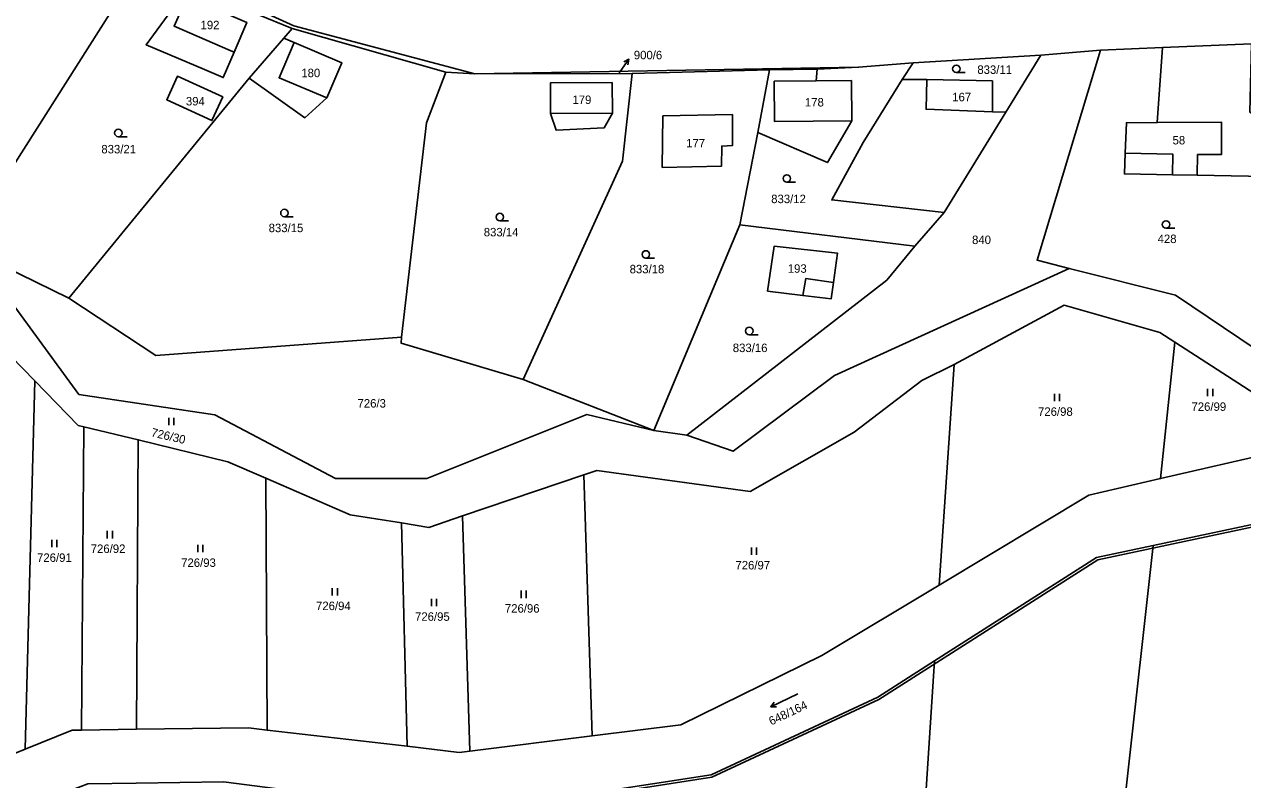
# Model space of a CAD drawing. Extents: x -654083 to -650132, y -1099819 to -1096699.
# Drawn here: x -652530.5 to -652286.2, y -1098583.8 to -1098432.3 of the extents above; entities that cross this region are included whole.
import ezdxf

# ---------------------------------------------------------------- set-up
doc = ezdxf.new("R2010")
doc.units = 0
for name, color, linetype in [('Hranice - vnitř_ kresba', 7, 'Continuous'), ('Obvody jako plochy', 7, 'Continuous'), ('Ostatní hranice', 7, 'Continuous'), ('Parcelní čísla', 7, 'Continuous'), ('Prvky pro prodl_ par_ č_', 7, 'Continuous'), ('Značky kultur', 7, 'Continuous')]:
    doc.layers.add(name, color=color, linetype=linetype)

msp = doc.modelspace()

# ---------------------------------------------------------------- linework, layer by layer
at = {"layer": 'Hranice - vnitř_ kresba'}
for p, q in [((-652497.86, -1098426.73), (-652500.48, -1098432.67)), ((-652500.48, -1098432.67), (-652489.23, -1098437.54)), ((-652489.23, -1098437.54), (-652488.44, -1098437.88)), ((-652476.41, -1098435.96), (-652479.41, -1098443.01)), ((-652479.41, -1098443.01), (-652469.86, -1098447.07)), ((-652380.17, -1098443.71), (-652371.72, -1098443.64)), ((-652380.17, -1098443.71), (-652380.11, -1098451.76)), ((-652349.71, -1098449.33), (-652349.57, -1098443.34)), ((-652349.71, -1098449.33), (-652336.41, -1098449.82)), ((-652424.99, -1098450.19), (-652412.59, -1098450.14)), ((-652380.11, -1098451.76), (-652364.62, -1098451.64)), ((-652303.36, -1098452.01), (-652290.45, -1098451.94)), ((-652290.5, -1098458.42), (-652290.45, -1098451.94)), ((-652309.8, -1098458.12), (-652300.27, -1098458.32)), ((-652300.27, -1098458.32), (-652300.32, -1098462.48)), ((-652295.28, -1098458.4), (-652295.33, -1098462.57)), ((-652295.28, -1098458.4), (-652290.5, -1098458.42)), ((-652373.84, -1098483.29), (-652374.4, -1098486.68)), ((-652368.28, -1098484.06), (-652373.84, -1098483.29))]:
    msp.add_line(p, q, dxfattribs=at)
at = {"layer": 'Obvody jako plochy'}
for points in [[(-652446, -1098441.91), (-652476.82, -1098433.16), (-652497.47, -1098424.65), (-652506.82, -1098419.78), (-652532.27, -1098406.94), (-652542.32, -1098403.58), (-652559.94, -1098399.93), (-652559.53, -1098399.2), (-652541.49, -1098401.98), (-652529.79, -1098405.93), (-652498.81, -1098422.38), (-652476.45, -1098432.57), (-652440.16, -1098442.2)], [(-652560.42, -1098472.15), (-652543.42, -1098477.5), (-652506.82, -1098419.78), (-652532.27, -1098406.94), (-652577.66, -1098473.77), (-652576.42, -1098473.9), (-652564.53, -1098474.44)], [(-652521.58, -1098487.25), (-652541.39, -1098477.54), (-652542.49, -1098478.23), (-652543.42, -1098477.5), (-652506.82, -1098419.78), (-652497.47, -1098424.65), (-652476.82, -1098433.16), (-652478.48, -1098435.08), (-652485.44, -1098443.08)], [(-652497.86, -1098426.73), (-652485.89, -1098431.92), (-652488.44, -1098437.88), (-652490.62, -1098442.98), (-652494.35, -1098441.39), (-652499.59, -1098439.16), (-652506.07, -1098436.4), (-652498.69, -1098426.32)], [(-652490.62, -1098442.98), (-652494.35, -1098441.39), (-652499.59, -1098439.16), (-652506.07, -1098436.4), (-652498.69, -1098426.32), (-652497.86, -1098426.73), (-652485.89, -1098431.92), (-652488.44, -1098437.88)], [(-652497.86, -1098426.73), (-652485.89, -1098431.92), (-652488.44, -1098437.88), (-652489.23, -1098437.54), (-652500.48, -1098432.67)], [(-652476.41, -1098435.96), (-652466.86, -1098440.02), (-652469.86, -1098447.07), (-652474.28, -1098451.05), (-652485.44, -1098443.08), (-652521.58, -1098487.25), (-652504.1, -1098498.73), (-652454.85, -1098495.04), (-652449.86, -1098452.04), (-652446, -1098441.91), (-652476.82, -1098433.16), (-652478.48, -1098435.08)], [(-652476.41, -1098435.96), (-652466.86, -1098440.02), (-652469.86, -1098447.07), (-652474.28, -1098451.05), (-652485.44, -1098443.08), (-652478.48, -1098435.08)], [(-652476.41, -1098435.96), (-652479.41, -1098443.01), (-652469.86, -1098447.07), (-652466.86, -1098440.02)], [(-652327.45, -1098479.59), (-652320.99, -1098481.27), (-652368.08, -1098502.78), (-652388.41, -1098517.93), (-652397.68, -1098514.75), (-652357.59, -1098483.61), (-652351.99, -1098476.81), (-652346.1, -1098470.06), (-652333.71, -1098449.89), (-652326.71, -1098438.51), (-652314.71, -1098437.5)], [(-652300.32, -1098462.48), (-652309.95, -1098462.31), (-652309.8, -1098458.12), (-652309.55, -1098452.04), (-652303.36, -1098452.01), (-652302.28, -1098436.98), (-652314.71, -1098437.5), (-652327.45, -1098479.59), (-652320.99, -1098481.27), (-652299.69, -1098486.62), (-652283.51, -1098497.52), (-652278.66, -1098489.27), (-652277.94, -1098487.45), (-652278.24, -1098462.86), (-652295.33, -1098462.57)], [(-652284.44, -1098436.24), (-652284.82, -1098449.89), (-652278.34, -1098454.23), (-652278.24, -1098462.86), (-652295.33, -1098462.57), (-652300.32, -1098462.48), (-652309.95, -1098462.31), (-652309.8, -1098458.12), (-652309.55, -1098452.04), (-652303.36, -1098452.01), (-652302.28, -1098436.98)], [(-652349.57, -1098443.34), (-652354.47, -1098443.38), (-652352.31, -1098440.04), (-652326.71, -1098438.51), (-652333.71, -1098449.89), (-652336.41, -1098449.82), (-652336.4, -1098443.65)], [(-652408.63, -1098442.14), (-652410.55, -1098459.73), (-652430.51, -1098503.52), (-652454.95, -1098496.23), (-652454.85, -1098495.04), (-652449.86, -1098452.04), (-652446, -1098441.91), (-652440.16, -1098442.2)], [(-652381.11, -1098441.42), (-652408.63, -1098442.14), (-652440.16, -1098442.2), (-652363.23, -1098440.91), (-652371.52, -1098441.29)], [(-652381.11, -1098441.42), (-652383.42, -1098453.97), (-652387.07, -1098472.53), (-652404.29, -1098513.75), (-652430.51, -1098503.52), (-652410.55, -1098459.73), (-652408.63, -1098442.14)], [(-652364.62, -1098451.64), (-652364.68, -1098443.59), (-652371.72, -1098443.64), (-652371.52, -1098441.29), (-652363.23, -1098440.91), (-652352.31, -1098440.04), (-652354.47, -1098443.38), (-652362.31, -1098456.02), (-652368.61, -1098467.51), (-652346.1, -1098470.06), (-652351.99, -1098476.81), (-652387.07, -1098472.53), (-652383.42, -1098453.97), (-652369.48, -1098460.02)], [(-652371.72, -1098443.64), (-652364.68, -1098443.59), (-652364.62, -1098451.64), (-652369.48, -1098460.02), (-652383.42, -1098453.97), (-652381.11, -1098441.42), (-652371.52, -1098441.29)], [(-652490.72, -1098446.87), (-652492.9, -1098451.61), (-652501.95, -1098447.42), (-652499.81, -1098442.71)], [(-652499.81, -1098442.71), (-652490.72, -1098446.87), (-652492.9, -1098451.61), (-652501.95, -1098447.42)], [(-652490.72, -1098446.87), (-652492.9, -1098451.61), (-652501.95, -1098447.42), (-652499.81, -1098442.71)], [(-652425.02, -1098444.06), (-652412.66, -1098444), (-652412.59, -1098450.14), (-652414.22, -1098453.05), (-652423.87, -1098453.5), (-652424.99, -1098450.19)], [(-652424.99, -1098450.19), (-652425.02, -1098444.06), (-652412.66, -1098444), (-652412.59, -1098450.14), (-652414.22, -1098453.05), (-652423.87, -1098453.5)], [(-652412.66, -1098444), (-652412.59, -1098450.14), (-652424.99, -1098450.19), (-652425.02, -1098444.06)], [(-652380.17, -1098443.71), (-652371.72, -1098443.64), (-652364.68, -1098443.59), (-652364.62, -1098451.64), (-652380.11, -1098451.76)], [(-652336.41, -1098449.82), (-652333.71, -1098449.89), (-652346.1, -1098470.06), (-652368.61, -1098467.51), (-652362.31, -1098456.02), (-652354.47, -1098443.38), (-652349.57, -1098443.34), (-652336.4, -1098443.65)], [(-652336.4, -1098443.65), (-652349.57, -1098443.34), (-652349.71, -1098449.33), (-652336.41, -1098449.82)], [(-652388.54, -1098456.63), (-652388.54, -1098450.42), (-652402.46, -1098450.66), (-652402.61, -1098461.01), (-652390.73, -1098460.76), (-652390.68, -1098456.73)], [(-652402.61, -1098461.01), (-652390.73, -1098460.76), (-652390.68, -1098456.73), (-652388.54, -1098456.63), (-652388.54, -1098450.42), (-652402.46, -1098450.66)], [(-652388.54, -1098456.63), (-652388.54, -1098450.42), (-652402.46, -1098450.66), (-652402.61, -1098461.01), (-652390.73, -1098460.76), (-652390.68, -1098456.73)], [(-652295.28, -1098458.4), (-652290.5, -1098458.42), (-652290.45, -1098451.94), (-652303.36, -1098452.01), (-652309.55, -1098452.04), (-652309.8, -1098458.12), (-652300.27, -1098458.32), (-652300.32, -1098462.48), (-652295.33, -1098462.57)], [(-652357.59, -1098483.61), (-652351.99, -1098476.81), (-652387.07, -1098472.53), (-652404.29, -1098513.75), (-652397.68, -1098514.75)], [(-652430.51, -1098503.52), (-652404.29, -1098513.75), (-652417.74, -1098510.6), (-652449.8, -1098523.41), (-652468.14, -1098523.44), (-652492.28, -1098510.63), (-652519.55, -1098506.55), (-652532.38, -1098488.94), (-652542.49, -1098478.23), (-652541.39, -1098477.54), (-652521.58, -1098487.25), (-652504.1, -1098498.73), (-652454.85, -1098495.04), (-652454.95, -1098496.23)], [(-652381.5, -1098485.8), (-652380.16, -1098476.8), (-652367.48, -1098478.2), (-652368.28, -1098484.06), (-652368.77, -1098487.38), (-652374.4, -1098486.68)], [(-652368.77, -1098487.38), (-652368.28, -1098484.06), (-652367.48, -1098478.2), (-652380.16, -1098476.8), (-652381.5, -1098485.8), (-652374.4, -1098486.68)], [(-652380.16, -1098476.8), (-652367.48, -1098478.2), (-652368.28, -1098484.06), (-652373.84, -1098483.29), (-652374.4, -1098486.68), (-652381.5, -1098485.8)], [(-652299.83, -1098496.09), (-652302.7, -1098523.43), (-652317.1, -1098526.74), (-652347.07, -1098544.78), (-652344.09, -1098500.53), (-652322.01, -1098488.66), (-652302.87, -1098494.09)], [(-652528.41, -1098503.85), (-652530.32, -1098577.7), (-652540.88, -1098581.95), (-652538.07, -1098493.95)], [(-652299.83, -1098496.09), (-652302.7, -1098523.43), (-652279.4, -1098518.06), (-652267.03, -1098517.28)], [(-652416.68, -1098575.03), (-652398.85, -1098572.81), (-652370.59, -1098558.94), (-652347.07, -1098544.78), (-652344.09, -1098500.53), (-652350.53, -1098503.77), (-652364.14, -1098514.09), (-652384.97, -1098526.01), (-652415.73, -1098521.81), (-652418.34, -1098522.69)], [(-652518.57, -1098513.04), (-652519.04, -1098573.87), (-652520.87, -1098573.89), (-652530.32, -1098577.7), (-652528.41, -1098503.85), (-652519.7, -1098512.77)], [(-652507.65, -1098515.64), (-652508.01, -1098573.73), (-652519.04, -1098573.87), (-652518.57, -1098513.04)], [(-652508.01, -1098573.73), (-652485.52, -1098573.45), (-652481.8, -1098573.88), (-652482.09, -1098523.34), (-652489.68, -1098520.05), (-652507.65, -1098515.64)], [(-652441.17, -1098578.09), (-652416.68, -1098575.03), (-652418.34, -1098522.69), (-652442.65, -1098530.93)], [(-652454.88, -1098532.33), (-652453.77, -1098577.14), (-652481.8, -1098573.88), (-652482.09, -1098523.34), (-652465.2, -1098530.67)], [(-652264.57, -1098533.1), (-652281.26, -1098681.4), (-652307.2, -1098682.68), (-652307.39, -1098684.23), (-652320.12, -1098679.86), (-652304.18, -1098536.87), (-652279, -1098531.51), (-652266.09, -1098528.97)], [(-652453.77, -1098577.14), (-652443.34, -1098578.36), (-652441.17, -1098578.09), (-652442.65, -1098530.93), (-652449.38, -1098533.21), (-652454.88, -1098532.33)], [(-652304.18, -1098536.87), (-652320.12, -1098679.86), (-652341.51, -1098673.02), (-652343.36, -1098672.43), (-652347.62, -1098659.13), (-652353.3, -1098641.38), (-652348.01, -1098560.01), (-652315.53, -1098539.28)], [(-652348.01, -1098560.01), (-652353.3, -1098641.38), (-652411.88, -1098662.18), (-652414.07, -1098662.96), (-652416.29, -1098586.5), (-652392.78, -1098582.87), (-652359.39, -1098567.27)]]:
    msp.add_lwpolyline(points, close=True, dxfattribs=at)
for points in [[(-652498.81, -1098422.38), (-652476.45, -1098432.57), (-652440.16, -1098442.2), (-652363.23, -1098440.91), (-652352.31, -1098440.04), (-652326.71, -1098438.51), (-652314.71, -1098437.5), (-652302.28, -1098436.98), (-652284.44, -1098436.24), (-652260.06, -1098435.58), (-652243.14, -1098435.37), (-652237.88, -1098435.44), (-652215.81, -1098435.75), (-652212.84, -1098435.79), (-652187.85, -1098434.22), (-652163.64, -1098428.58)], [(-652532.38, -1098488.94), (-652519.55, -1098506.55), (-652492.28, -1098510.63), (-652468.14, -1098523.44), (-652449.8, -1098523.41), (-652417.74, -1098510.6), (-652404.29, -1098513.75), (-652397.68, -1098514.75), (-652388.41, -1098517.93), (-652368.08, -1098502.78), (-652320.99, -1098481.27), (-652299.69, -1098486.62), (-652283.51, -1098497.52)], [(-652267.03, -1098517.28), (-652299.83, -1098496.09), (-652302.87, -1098494.09), (-652322.01, -1098488.66), (-652344.09, -1098500.53), (-652350.53, -1098503.77), (-652364.14, -1098514.09), (-652384.97, -1098526.01), (-652415.73, -1098521.81), (-652418.34, -1098522.69), (-652442.65, -1098530.93), (-652449.38, -1098533.21), (-652454.88, -1098532.33), (-652465.2, -1098530.67), (-652482.09, -1098523.34), (-652489.68, -1098520.05), (-652507.65, -1098515.64), (-652518.57, -1098513.04), (-652519.7, -1098512.77), (-652528.41, -1098503.85), (-652538.07, -1098493.95)], [(-652279.4, -1098518.06), (-652302.7, -1098523.43), (-652317.1, -1098526.74), (-652347.07, -1098544.78), (-652370.59, -1098558.94), (-652398.85, -1098572.81), (-652416.68, -1098575.03), (-652441.17, -1098578.09), (-652443.34, -1098578.36), (-652453.77, -1098577.14), (-652481.8, -1098573.88), (-652485.52, -1098573.45), (-652508.01, -1098573.73), (-652519.04, -1098573.87), (-652520.87, -1098573.89), (-652530.32, -1098577.7), (-652540.88, -1098581.95)], [(-652530.65, -1098589.56), (-652519.14, -1098585.18), (-652517.75, -1098584.65), (-652508.06, -1098584.52), (-652490.53, -1098584.29), (-652481.75, -1098585.43), (-652453.47, -1098589.12), (-652442.53, -1098590.55), (-652440.94, -1098590.3), (-652416.29, -1098586.5), (-652392.78, -1098582.87), (-652359.39, -1098567.27), (-652348.01, -1098560.01), (-652315.53, -1098539.28), (-652304.18, -1098536.87), (-652279, -1098531.51)]]:
    msp.add_lwpolyline(points, dxfattribs=at)
at = {"layer": 'Ostatní hranice'}
for p, q in [((-652315.3, -1098539.73), (-652278.84, -1098531.98)), ((-652359.17, -1098567.72), (-652315.3, -1098539.73)), ((-652392.66, -1098583.36), (-652359.17, -1098567.72)), ((-652442.5, -1098591.05), (-652392.66, -1098583.36))]:
    msp.add_line(p, q, dxfattribs=at)
at = {"layer": 'Prvky pro prodl_ par_ č_'}
for p, q in [((-652411.07, -1098441.73), (-652409.3, -1098439.31)), ((-652411.27, -1098442.01), (-652411.07, -1098441.73))]:
    msp.add_line(p, q, dxfattribs=at)
msp.add_lwpolyline([(-652410.3, -1098439.82), (-652409.3, -1098439.31), (-652409.49, -1098440.41)], dxfattribs=at)
at = {"layer": 'Značky kultur'}
for p, q in [((-652341.89, -1098441.97), (-652343.64, -1098441.97)), ((-652509.9, -1098454.84), (-652511.65, -1098454.84)), ((-652375.88, -1098463.98), (-652377.63, -1098463.98)), ((-652476.6, -1098470.9), (-652478.35, -1098470.9)), ((-652433.42, -1098471.71), (-652435.17, -1098471.71)), ((-652299.85, -1098473.21), (-652301.6, -1098473.21)), ((-652404.15, -1098479.21), (-652405.9, -1098479.21)), ((-652383.4, -1098494.56), (-652385.15, -1098494.56)), ((-652293.26, -1098505.41), (-652293.26, -1098506.91)), ((-652292.23, -1098506.91), (-652292.23, -1098505.41)), ((-652323.99, -1098506.41), (-652323.99, -1098507.91)), ((-652322.96, -1098507.91), (-652322.96, -1098506.41)), ((-652501.55, -1098511.24), (-652501.55, -1098512.74)), ((-652500.53, -1098512.74), (-652500.53, -1098511.24)), ((-652513.87, -1098533.92), (-652513.87, -1098535.42)), ((-652512.84, -1098535.42), (-652512.84, -1098533.92)), ((-652525, -1098535.71), (-652525, -1098537.21)), ((-652523.97, -1098537.21), (-652523.97, -1098535.71)), ((-652495.72, -1098536.72), (-652495.72, -1098538.22)), ((-652494.7, -1098538.22), (-652494.7, -1098536.72)), ((-652384.72, -1098537.22), (-652384.72, -1098538.72)), ((-652383.7, -1098538.72), (-652383.7, -1098537.22)), ((-652468.76, -1098545.38), (-652468.76, -1098546.88)), ((-652467.73, -1098546.88), (-652467.73, -1098545.38)), ((-652430.9, -1098545.89), (-652430.9, -1098547.39)), ((-652429.88, -1098547.39), (-652429.88, -1098545.89)), ((-652448.87, -1098547.52), (-652448.87, -1098549.02)), ((-652447.84, -1098549.02), (-652447.84, -1098547.52)), ((-652375.42, -1098566.63), (-652380.84, -1098569.19))]:
    msp.add_line(p, q, dxfattribs=at)
msp.add_lwpolyline([(-652379.73, -1098569.21), (-652380.84, -1098569.19), (-652380.15, -1098568.31)], dxfattribs=at)
for centre in [(-652343.64, -1098441.22), (-652511.65, -1098454.09), (-652377.63, -1098463.23), (-652478.35, -1098470.15), (-652435.17, -1098470.96), (-652301.6, -1098472.46), (-652405.9, -1098478.46), (-652385.15, -1098493.81)]:
    msp.add_circle(centre, 0.75, dxfattribs=at)

# ---------------------------------------------------------------- texts
at = {"layer": 'Parcelní čísla'}
for s, height, p in [('192', 1.7, (-652495.16, -1098433.28)), ('180', 1.7, (-652474.96, -1098442.9)), ('900/6', 0.1, (-652411.27, -1098442.01)), ('833/11', 1.7, (-652339.43, -1098442.24)), ('394', 1.7, (-652498.1, -1098448.57)), ('179', 1.7, (-652420.61, -1098448.28)), ('178', 1.7, (-652374, -1098448.78)), ('167', 1.7, (-652344.47, -1098447.74)), ('833/21', 1.7, (-652515.05, -1098458.19)), ('177', 1.7, (-652397.8, -1098456.99)), ('58', 1.7, (-652300.29, -1098456.39)), ('833/12', 1.7, (-652380.76, -1098468.17)), ('833/15', 1.7, (-652481.51, -1098473.99)), ('833/14', 1.7, (-652438.38, -1098474.84)), ('840', 1.7, (-652340.49, -1098476.38)), ('428', 1.7, (-652303.29, -1098476.18)), ('833/18', 1.7, (-652409.14, -1098482.25)), ('193', 1.7, (-652377.44, -1098482.14)), ('833/16', 1.7, (-652388.46, -1098498.05)), ('726/3', 1.7, (-652463.69, -1098509.18)), ('726/99', 1.7, (-652296.5, -1098509.84)), ('726/98', 1.7, (-652327.26, -1098510.84)), ('726/92', 1.7, (-652517.18, -1098538.35)), ('726/91', 1.7, (-652527.94, -1098540.14)), ('726/93', 1.7, (-652499.05, -1098541.15)), ('726/97', 1.7, (-652387.93, -1098541.65)), ('726/94', 1.7, (-652472.01, -1098549.81)), ('726/96', 1.7, (-652434.15, -1098550.32)), ('726/95', 1.7, (-652452.16, -1098551.96))]:
    msp.add_text(s, height=height, dxfattribs=at).set_placement(p)
for s, rotation, p in [('726/30', 346.761, (-652505.18, -1098514.92)), ('648/164', 25.389, (-652380.74, -1098572.98))]:
    msp.add_text(s, height=1.7, rotation=rotation, dxfattribs=at).set_placement(p)
at = {"layer": 'Prvky pro prodl_ par_ č_'}
msp.add_text('900/6', height=1.7, dxfattribs=at).set_placement((-652408.3, -1098439.31))

doc.saveas('drawing.dxf')
